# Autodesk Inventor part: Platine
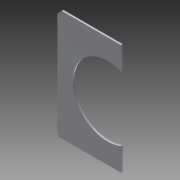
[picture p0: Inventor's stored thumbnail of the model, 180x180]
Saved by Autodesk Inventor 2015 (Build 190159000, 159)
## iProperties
Created: 2015-03
Part Number: Platine
Material: PVC, hart
Document SubType Name: Modeling
Designer: Andreas
Density: 1.29 g/cm^3
Appearance: Glatt - weiß
Author: Andreas
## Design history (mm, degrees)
sketch "Skizze1"
  geometry: L1 (0, 0)-(67, 0); L2 (72, -5)-(72, -123); L3 (70, -125)-(0, -125); L4 (0, -125)-(0, -99); L5 (0, 0)-(0, -26); L6 (70, -125)-(72, -123); L7 (67, 0)-(72, -5); A1 r 39.5 centre (15.1, -62.5) between (0, -99) and (0, -26); 3 further points
  constraints: 14 end point, 4 point on line, 3 perpendicular, 2 point on circle, 1 centre point, 1 coincident, 1 horizontal, 1 vertical
  dimensions: "d0" = 72 distance of L1.start point (72, 0); "d1" = 125 distance of point (72, 0) point (72, -125); "d2" = 72 distance of point (72, -125) L3.end; "d3" = 26 distance of L3.end L4.end; "d4" = 26 distance of L1.start L5.end; "d6" = 39.5 radius of A1; "d9" = 2 distance of L3.start point (72, -125); "d10" = 2 distance of L2.end point (72, -125) (= d9); "d11" = 5 distance of L1.end point (72, 0); "d12" = 5 distance of L2.start point (72, 0) (= d11)
extrude "Extrusion1" new body sketch "Skizze1" distance "d7" = 2; taper "d8" = 0 deg
node "Volumenkörper1"
